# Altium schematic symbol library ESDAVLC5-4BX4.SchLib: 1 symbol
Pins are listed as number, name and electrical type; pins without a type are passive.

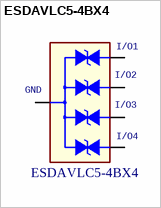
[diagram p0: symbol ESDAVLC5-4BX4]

## ESDAVLC5-4BX4
designator D?
footprint ST_CSP5_80x80x35
pins: 1 I/O1, 2 I/O2, 3 I/O3, 4 I/O4, 5 GND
